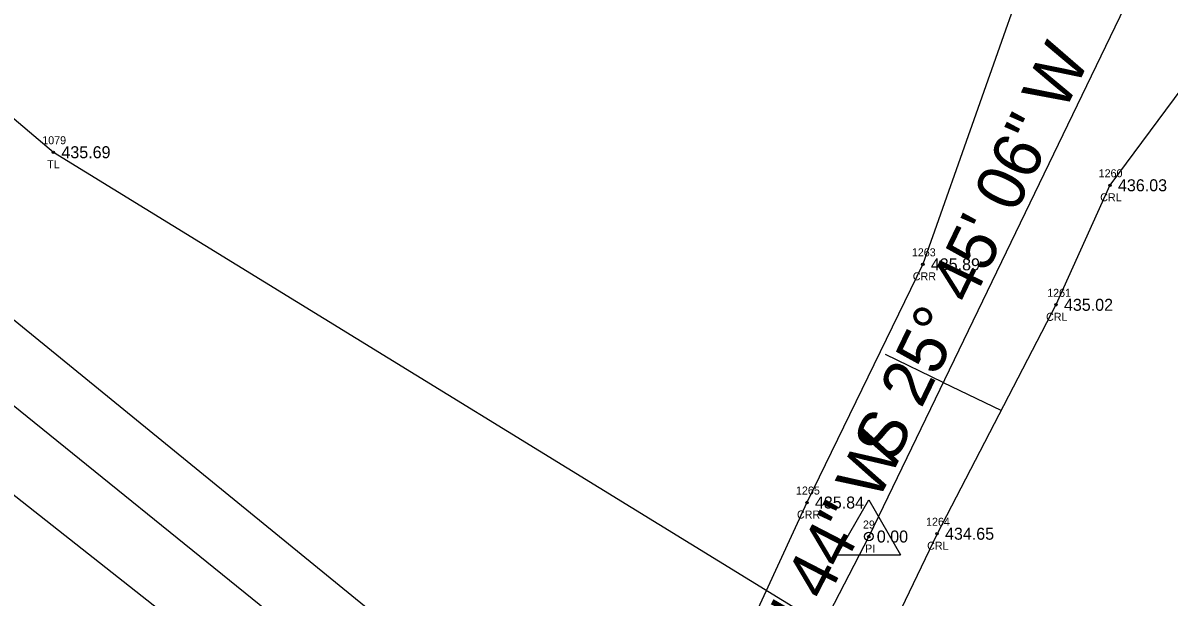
# Model space of a CAD drawing. Extents: x 1611865 to 1617004, y 775289 to 778546.
# Drawn here: x 1614381.3 to 1614524.5, y 777738.1 to 777809.8 of the extents above; entities that cross this region are included whole.
import ezdxf

# ---------------------------------------------------------------- set-up
doc = ezdxf.new("R2010")
doc.units = 0
for name, color, linetype in [('Default', 7, 'Continuous'), ('RD_EX_H2O', 7, 'Continuous'), ('RD_EX_H2O_txCode', 7, 'Continuous'), ('RD_EX_Road', 7, 'Continuous'), ('RD_EX_TX_H2O_ELEV', 7, 'Continuous'), ('RD_EX_TX_VEG_ELEV', 7, 'Continuous'), ('RD_EX_VEG', 7, 'Continuous'), ('RD_EX_VEG_txCode', 7, 'Continuous'), ('RD_HC_Cl', 7, 'Continuous'), ('RD_HC_Data', 7, 'Continuous'), ('RD_HC_Data_Tic', 7, 'Continuous'), ('RD_HC_Survey_ELEV', 7, 'Continuous'), ('RD_HC_txCode', 7, 'Continuous'), ('RD_SMD_Locator', 7, 'Continuous')]:
    doc.layers.add(name, color=color, linetype=linetype)

msp = doc.modelspace()

# ---------------------------------------------------------------- linework, layer by layer
at = {"layer": 'Default'}
for p, q in [((1614235.77, 777878.84), (1615250.56, 777057.49)), ((1614520.17, 777814.37), (1614487, 777745.62)), ((1614487, 777745.62), (1614472.45, 777717.46))]:
    msp.add_line(p, q, dxfattribs=at)
at = {"layer": 'RD_EX_H2O'}
for points in [[(1614634.13, 778230.42), (1614629.46, 778175.6), (1614612.2, 778126.55), (1614606.67, 778108.17), (1614610.57, 778089.24), (1614615.98, 778055.09), (1614603.68, 778033.92), (1614586.84, 777977.49), (1614567.11, 777927.46), (1614559.23, 777908.74), (1614527.56, 777868.79), (1614521.38, 777849.92), (1614508, 777820.03), (1614493.75, 777779.64), (1614479.27, 777749.87), (1614469.02, 777727.63), (1614464.37, 777721.67), (1614444.52, 777689.77), (1614435.76, 777671.49), (1614423.17, 777629.21)], [(1614612.84, 778001.09), (1614602.8, 777969.59), (1614583.96, 777919.69), (1614574.96, 777902.32), (1614550.82, 777861.38), (1614543.23, 777842.17), (1614528.68, 777813.75), (1614526.1, 777801.65), (1614517.13, 777789.52), (1614510.38, 777774.58), (1614495.52, 777745.97), (1614480.57, 777714.78), (1614474.46, 777705.96), (1614477.93, 777705.13), (1614481.15, 777703.4), (1614481.27, 777700.99), (1614480.97, 777699.74), (1614478.44, 777696.16), (1614475.82, 777697.62), (1614468.32, 777689.25), (1614463.06, 777676.24), (1614459.87, 777668.19), (1614440.89, 777623.61)]]:
    msp.add_lwpolyline(points, dxfattribs=at)
at = {"layer": 'RD_EX_Road'}
for points in [[(1613868.87, 778104.15), (1613915.02, 778083.82), (1613960.16, 778062.2), (1614004.58, 778040.28), (1614048.84, 778015.98), (1614091.38, 777990.08), (1614134.36, 777962.6), (1614174.73, 777933.48), (1614192.07, 777920.58), (1614215.93, 777904.23), (1614254.59, 777873.05), (1614293.82, 777842.42), (1614371.74, 777779.59), (1614449.33, 777716.3), (1614443.98, 777709.72), (1614439.38, 777704.09)], [(1613862.14, 778087.92), (1613908.12, 778068.22), (1613952.96, 778047.38), (1613997, 778025.09), (1614041.16, 778001.63), (1614124.35, 777949.06), (1614164.51, 777920.91), (1614187.11, 777904.29), (1614205.27, 777889.82), (1614244.49, 777859.52), (1614283.42, 777829.45), (1614361.06, 777765.89), (1614439.38, 777704.09)]]:
    msp.add_lwpolyline(points, dxfattribs=at)
at = {"layer": 'RD_EX_VEG'}
msp.add_lwpolyline([(1613877.31, 778121.22), (1613921.05, 778100.02), (1613970.15, 778081.54), (1614014.03, 778056.89), (1614062.61, 778034.99), (1614105.06, 778008.15), (1614147.57, 777982.51), (1614187.98, 777952.84), (1614226.4, 777922.61), (1614267.62, 777889.85), (1614307.16, 777859.76), (1614385.12, 777793.65), (1614491.14, 777728.5)], dxfattribs=at)
at = {"layer": 'RD_HC_Cl'}
for p, q in [((1614235.77, 777878.84), (1615250.56, 777057.49)), ((1614520.17, 777814.37), (1614487, 777745.62)), ((1614487, 777745.62), (1614472.45, 777717.46))]:
    msp.add_line(p, q, dxfattribs=at)
at = {"layer": 'RD_HC_Data'}
for p, q in [((1614483.03, 777743.33), (1614487, 777750.21)), ((1614487, 777750.21), (1614490.97, 777743.33)), ((1614483.03, 777743.33), (1614490.97, 777743.33))]:
    msp.add_line(p, q, dxfattribs=at)
msp.add_circle((1614487, 777745.62), 0.529, dxfattribs=at)
at = {"layer": 'RD_HC_Data_Tic'}
for q in [(1614489.09, 777768.37), (1614503.5, 777761.41)]:
    msp.add_line((1614496.3, 777764.89), q, dxfattribs=at)
at = {"layer": 'RD_SMD_Locator'}
for centre in [(1614385.12, 777793.65), (1614517.13, 777789.52), (1614493.75, 777779.64), (1614510.38, 777774.58), (1614479.27, 777749.87), (1614495.52, 777745.97), (1614487, 777745.62)]:
    msp.add_circle(centre, 0.15, dxfattribs=at)

# ---------------------------------------------------------------- texts
at = {"layer": 'RD_EX_H2O_txCode'}
for s, p in [('1260', (1614515.72, 777790.52)), ('CRL', (1614515.91, 777787.52)), ('1263', (1614492.38, 777780.64)), ('CRR', (1614492.5, 777777.64)), ('1261', (1614509.29, 777775.58)), ('CRL', (1614509.15, 777772.58)), ('1265', (1614477.9, 777750.87)), ('CRR', (1614478.02, 777747.87)), ('1264', (1614494.15, 777746.97)), ('CRL', (1614494.29, 777743.97))]:
    msp.add_text(s, height=1, dxfattribs=at).set_placement(p)
at = {"layer": 'RD_EX_TX_H2O_ELEV'}
for s, p in [('436.03', (1614518.13, 777788.77)), ('435.89', (1614494.75, 777778.89)), ('435.02', (1614511.38, 777773.83)), ('435.84', (1614480.27, 777749.12)), ('434.65', (1614496.52, 777745.22))]:
    msp.add_text(s, height=1.5, dxfattribs=at).set_placement(p)
at = {"layer": 'RD_EX_TX_VEG_ELEV'}
msp.add_text('435.69', height=1.5, dxfattribs=at).set_placement((1614386.12, 777792.9))
at = {"layer": 'RD_EX_VEG_txCode'}
for s, p in [('1079', (1614383.73, 777794.65)), ('TL', (1614384.34, 777791.65))]:
    msp.add_text(s, height=1, dxfattribs=at).set_placement(p)
at = {"layer": 'RD_HC_Data'}
for s, rotation, p in [('S 25%%d 45\' 06" W', 64.2484, (1614490.26, 777754.68)), ('S 27%%d 19\' 44" W', 62.6712, (1614465.72, 777706.61))]:
    msp.add_text(s, height=6, rotation=rotation, dxfattribs=at).set_placement(p)
at = {"layer": 'RD_HC_Survey_ELEV'}
msp.add_text('0.00', height=1.5, dxfattribs=at).set_placement((1614488, 777744.87))
at = {"layer": 'RD_HC_txCode'}
for s, p in [('29', (1614486.27, 777746.62)), ('PI', (1614486.53, 777743.62))]:
    msp.add_text(s, height=1, dxfattribs=at).set_placement(p)

doc.saveas('drawing.dxf')
